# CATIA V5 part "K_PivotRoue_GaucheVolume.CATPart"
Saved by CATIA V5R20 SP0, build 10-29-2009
Part number: pivot_roue_gauche_volume
Publications: "Corps principal", "Face"
Bounding box of the stored display mesh (mm): x -30 to 30, y 426.667 to 635, z -19.994 to 19.994
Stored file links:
  G:\Khaled_CFAO_2011\ST2M\ST2M_GR1\cdurantin\cdurantin\Khaled\CAD_ThinkMOTION\K_PivotRoue_GaucheVolume.CATPart
  C:\Documents and Settings\cdurantin\Bureau\cdurantin\caddy.CATProduct
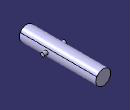
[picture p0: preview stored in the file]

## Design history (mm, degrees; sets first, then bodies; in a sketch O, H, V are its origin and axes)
External parameters (linked from other documents)
  `External.diamètre des barres` = 40 mm
  `External.Surepaisseur du tube` = 10 mm
  `External.largeur pivot` = 125 mm
  `External.Longueur de barres du corps` = 800 mm
  `External.largeur de la glissière` = 100 mm
Set1
  DatumSurface1: linked copy from another document
  Line1: linked copy from another document
Body1 (main body)
  Sketch1 on xy-plane, origin (0, 0, 0), H (1, 0, 0), V (0, 1, 0)
    point P1 (0, 635)
    line L1 (0, 635) -> (20, 635)
    line L2 (20, 635) -> (20, 426.6667)
    line L3 (20, 426.6667) -> (0, 426.6667)
    line L4 (0, 426.6667) -> (0, 635)
    length L1 = 20 {= `External.diamètre des barres` /2}
    distance H L1 = 635 {= `External.Longueur de barres du corps` /2+`External.largeur de la glissière` +`External.largeur pivot` +`External.Surepaisseur du tube`}
    length L2 = 208.3333 {= `External.largeur pivot` +`External.diamètre des barres` +`External.Surepaisseur du tube`+`External.largeur de la glissière` /3}
    coincidence: P1 V
    horizontal: L1 H, L3 H
    vertical: L2 V, L4 V
  Shaft1: profile Sketch1, axis Sketch1.L4, angle 360
  Sketch2 on face of DatumSurface1, origin (30, 0, 0), H (0, -1, 0), V (0, 0, 1)
    circle A1 centre (-500, 0) radius 5
    reference projected point E1 (-500, 0) from Line1
    radius A1 = 5 {= `External.Surepaisseur du tube` /2}
    concentricity: A1 E1
  Pad1: profile Sketch2, direction (-1, 0, 0), up to face of Shaft1 from Sketch1.L2
  Mirror1: of Pad1, about yz-plane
